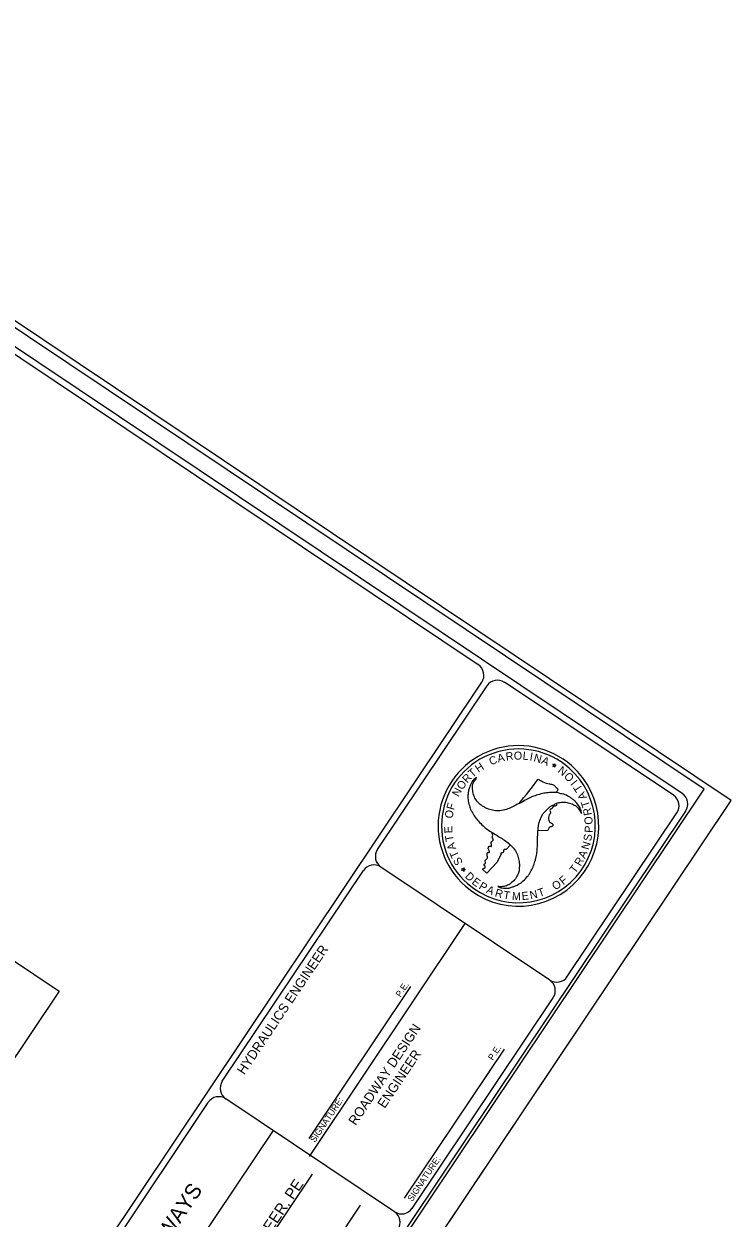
# Model space of a CAD drawing. Extents: x 1715610 to 1720914, y 798298 to 802505.
# Drawn here: x 1717939 to 1718775, y 801094 to 802505 of the extents above; entities that cross this region are included whole.
import ezdxf

# ---------------------------------------------------------------- set-up
doc = ezdxf.new("R2010")
doc.units = 0
for name, color, linetype in [('Prop DSN Text', 7, 'Continuous'), ('Sheet Cutting Line CELL', 7, 'Continuous'), ('Sheet Data Field CELL', 7, 'Continuous'), ('Sheet Plot Border Inside CELL', 7, 'Continuous'), ('Sheet Plot Border Outside CELL', 7, 'Continuous'), ('Sheet Title CELL', 7, 'Continuous')]:
    doc.layers.add(name, color=color, linetype=linetype)

msp = doc.modelspace()

# ---------------------------------------------------------------- linework, layer by layer
at = {"layer": 'Prop DSN Text'}
msp.add_lwpolyline([(1717114.5, 800787.1), (1717648.2, 801584.4), (1717980.5, 801362), (1717446.8, 800564.7)], close=True, dxfattribs=at)
at = {"layer": 'Sheet Cutting Line CELL'}
msp.add_line((1717369.7, 799488.2), (1718774.7, 801587.4), dxfattribs=at)
at = {"layer": 'Sheet Plot Border Inside CELL'}
msp.add_lwpolyline([(1717352.6, 799523.2), (1718743, 801600.5), (1717427.7, 802480.8), (1716037.3, 800403.5)], close=True, dxfattribs=at)
at = {"layer": 'Sheet Plot Border Outside CELL'}
msp.add_lwpolyline([(1717403.5, 802505.2), (1715998.5, 800406), (1717369.7, 799488.2), (1718774.7, 801587.4)], close=True, dxfattribs=at)
at = {"layer": 'Sheet Title CELL'}
for p, q in [((1717295.2, 799956.8), (1718480, 801726.9)), ((1718356.7, 801529.2), (1718486.2, 801722.7)), ((1718564.9, 801628.7), (1718563.8, 801627.5)), ((1718563.8, 801627.5), (1718565.4, 801627.9)), ((1718565.6, 801629.5), (1718564.1, 801630.1)), ((1718564.1, 801630.1), (1718564.9, 801628.7)), ((1718565.4, 801627.9), (1718566.3, 801626.5)), ((1718566.6, 801630.7), (1718565.6, 801629.5)), ((1718566.3, 801626.5), (1718566.4, 801628)), ((1718566.4, 801628), (1718568, 801628.4)), ((1718566.5, 801629.1), (1718566.6, 801630.7)), ((1718568, 801628.4), (1718566.5, 801629.1)), ((1718586, 801628.4), (1718586, 801628.4)), ((1718473.6, 801614.5), (1718473.6, 801614.2)), ((1718473.6, 801614.5), (1718473.6, 801614.2)), ((1718524, 801583.6), (1718524, 801583.6)), ((1718558.2, 801551.7), (1718546.4, 801551.4)), ((1718546.4, 801551.4), (1718546.4, 801551.4)), ((1718513.9, 801534.7), (1718508.9, 801529.1)), ((1718502.8, 801524), (1718498.2, 801514.2)), ((1718173.3, 801255.3), (1718340, 801504.3)), ((1718560.3, 801374.9), (1718360.8, 801508.4)), ((1718456.1, 801504.4), (1718457.2, 801505.7)), ((1718457.8, 801504.8), (1718456.1, 801504.4)), ((1718457.2, 801505.7), (1718456.4, 801507)), ((1718456.4, 801507), (1718457.9, 801506.4)), ((1718458.6, 801503.4), (1718457.8, 801504.8)), ((1718457.9, 801506.4), (1718459, 801507.7)), ((1718458.7, 801505), (1718458.6, 801503.4)), ((1718460.3, 801505.3), (1718458.7, 801505)), ((1718459, 801507.7), (1718458.8, 801506)), ((1718458.8, 801506), (1718460.3, 801505.3)), ((1718485.8, 801501.2), (1718481.7, 801505.1)), ((1718498.2, 801514.2), (1718485.8, 801501.2)), ((1718276.4, 801166.6), (1718460.5, 801441.7)), ((1718276, 801187.5), (1718396.3, 801367.3)), ((1718388.7, 801117), (1718506.7, 801293.4)), ((1717918.9, 800875.1), (1718156.7, 801230.4)), ((1718376.9, 801101), (1718177.5, 801234.5)), ((1718233.3, 801197.1), (1717978.8, 800816.9)), ((1718150.4, 800952), (1718279.8, 801145.4)), ((1718206.2, 800914), (1718336.6, 801108.8))]:
    msp.add_line(p, q, dxfattribs=at)
for points in [[(1718716.9, 801595.4), (1717432.9, 802454.8)], [(1718475.9, 801747.7), (1717435, 802444.4)], [(1718706.5, 801593.4), (1718507, 801726.9)], [(1717486.2, 799729.7), (1718721, 801574.6)], [(1718581.1, 801379.1), (1718710.6, 801572.6)], [(1718397.7, 801105.1), (1718564.4, 801354.1)]]:
    msp.add_lwpolyline(points, dxfattribs=at)
for centre, radius, start, end in [((1718467.5, 801735.3), 15, 326.2051, 56.2051), ((1718498.6, 801714.4), 15, 56.2051, 146.2051), ((1718523.3, 801557.2), 94.9, 48.6262, 228.6262), ((1718523.3, 801557.2), 90.9, 48.6262, 228.6262), ((1718523.3, 801557.2), 94.9, 228.6262, 48.6262), ((1718523.3, 801557.2), 90.9, 228.6262, 48.6262), ((1718142.2, 801906.9), 500.3, 319.7437, 323.9497), ((1718698.1, 801580.9), 15, 326.2051, 56.2051), ((1718708.5, 801583), 15, 326.2051, 56.2051), ((1718142.2, 801906.9), 500.3, 314.3047, 314.4043), ((1718369.2, 801520.9), 15, 146.2051, 236.2051), ((1718352.5, 801496), 15, 56.2051, 146.2051), ((1718568.6, 801387.5), 15, 236.2051, 326.2051), ((1718551.9, 801362.5), 15, 326.2051, 56.2051), ((1718185.8, 801247), 15, 146.2051, 236.2051), ((1718169.1, 801222.1), 15, 56.2051, 146.2051), ((1718385.2, 801113.5), 15, 236.2051, 326.2051), ((1718368.5, 801088.6), 15, 326.2051, 56.2051)]:
    msp.add_arc(centre, radius, start, end, dxfattribs=at)
for points in [[(1718473.6, 801614.2), (1718471.8, 801613), (1718467.8, 801608.1), (1718465.1, 801601.9), (1718464.9, 801601.3), (1718464.1, 801597.8), (1718463.7, 801593.5), (1718464, 801586.5), (1718465.9, 801579.5), (1718466.8, 801576.7), (1718468.4, 801573.7), (1718472, 801567.7), (1718476.1, 801562.6), (1718481.5, 801557.3), (1718486.6, 801553), (1718492.4, 801549.3), (1718498.3, 801545.7), (1718503.9, 801542.1), (1718509.7, 801538.2), (1718514.8, 801533.8), (1718515.2, 801533.4), (1718519.8, 801527.7), (1718522.6, 801521.3), (1718524.1, 801515), (1718524.5, 801511.7), (1718524.3, 801507.7), (1718524.2, 801505.4), (1718523, 801500.7), (1718519.8, 801494.8), (1718515.3, 801490.3), (1718510.5, 801487), (1718504.9, 801485.4), (1718498.9, 801485.5)], [(1718597.7, 801571.8), (1718597.6, 801573.9), (1718595.3, 801579.8), (1718591.3, 801585.3), (1718590.9, 801585.8), (1718588.2, 801588.2), (1718584.7, 801590.6), (1718578.5, 801594), (1718571.6, 801595.7), (1718568.7, 801596.5), (1718565.2, 801596.6), (1718558.3, 801596.4), (1718551.8, 801595.4), (1718544.5, 801593.4), (1718538.3, 801591.1), (1718532.1, 801587.9), (1718526.1, 801584.6), (1718520.1, 801581.6), (1718513.9, 801578.5), (1718507.5, 801576.3), (1718506.9, 801576.2), (1718499.6, 801575), (1718492.7, 801575.8), (1718486.5, 801577.6), (1718483.5, 801579), (1718480.1, 801581.2), (1718478.1, 801582.4), (1718474.8, 801585.8), (1718471.2, 801591.5), (1718469.5, 801597.6), (1718469.1, 801603.4), (1718470.6, 801609.1), (1718473.6, 801614.2), (1718473.6, 801614.5)], [(1718546.7, 801612.4), (1718552.3, 801609.3), (1718560.1, 801606.8), (1718564.6, 801605.7), (1718567.2, 801603.4), (1718569.8, 801600), (1718567.4, 801596.7)], [(1718567.4, 801596.6), (1718565.2, 801596.6), (1718558.3, 801596.4), (1718551.8, 801595.4), (1718544.5, 801593.4), (1718538.3, 801591.1), (1718532.1, 801587.9), (1718526.1, 801584.6), (1718524, 801583.6)], [(1718498.9, 801485.5), (1718500.9, 801484.6), (1718507.1, 801483.5), (1718513.8, 801484.2), (1718514.4, 801484.5), (1718518, 801485.5), (1718521.7, 801487.3), (1718527.8, 801491), (1718532.7, 801496.1), (1718534.8, 801498.3), (1718536.7, 801501.3), (1718539.9, 801507.3), (1718542.3, 801513.4), (1718544.2, 801520.8), (1718545.4, 801527.3), (1718545.7, 801534.2), (1718545.8, 801541.1), (1718546.2, 801547.8), (1718546.7, 801554.7), (1718548, 801561.4), (1718548.2, 801562), (1718550.8, 801568.9), (1718554.9, 801574.4), (1718559.5, 801578.9), (1718562.3, 801580.9), (1718565.9, 801582.6), (1718567.9, 801583.8), (1718572.6, 801585), (1718579.2, 801585.2), (1718585.3, 801583.6), (1718590.6, 801581.1), (1718594.8, 801577), (1718597.7, 801571.8)], [(1718546.4, 801551.4), (1718546.7, 801554.7), (1718548, 801561.4), (1718548.2, 801562), (1718550.8, 801568.9), (1718554.9, 801574.4), (1718559.5, 801578.9), (1718562.3, 801580.9), (1718565.9, 801582.6), (1718567.8, 801583.7)], [(1718567.8, 801583.7), (1718568.5, 801581.9), (1718567.6, 801580.8), (1718564.5, 801580.2), (1718562.9, 801577.5), (1718561.4, 801577), (1718560.7, 801576.3), (1718561.3, 801572.8), (1718559.8, 801570.1), (1718559.3, 801564), (1718560.2, 801561.8), (1718563.9, 801559.1), (1718563.8, 801557.6), (1718562.6, 801556.6), (1718559.7, 801555.1), (1718558.2, 801551.7)], [(1718481.7, 801505.1), (1718481.1, 801505.3), (1718481.3, 801506.4), (1718483.9, 801507.7), (1718483.9, 801509.5), (1718483, 801510.2), (1718482.9, 801511.8), (1718484.3, 801512.9), (1718483.9, 801515.5), (1718484.6, 801516.9), (1718486.7, 801519.3), (1718486.3, 801524.7), (1718487.2, 801526), (1718488.3, 801525.7), (1718489, 801526.3), (1718487.8, 801529.6), (1718487.7, 801530.2), (1718488.8, 801533.2), (1718489.7, 801533.4), (1718490.9, 801532.7), (1718491.4, 801532.8), (1718491.5, 801534), (1718491.2, 801536.1), (1718491.8, 801538.8), (1718493.9, 801540.7), (1718492.5, 801542.5), (1718493, 801546.4), (1718492.5, 801547.8), (1718491.6, 801548.8)], [(1718492.2, 801549.4), (1718492.4, 801549.3), (1718498.3, 801545.7), (1718503.9, 801542.1), (1718509.7, 801538.2), (1718513.9, 801534.7)], [(1718508.9, 801529.1), (1718507.4, 801529.5), (1718506.1, 801528.7), (1718505.6, 801526.5), (1718504.5, 801525.5), (1718502.6, 801525), (1718502.8, 801524)]]:
    msp.add_spline(points, degree=3, dxfattribs=at)

# ---------------------------------------------------------------- texts
at = {"layer": 'Sheet Data Field CELL'}
msp.add_text('JAMES A. SPEER, PE', height=13.125, rotation=56.2051, dxfattribs=at).set_placement((1718171.2, 800986.5))
at = {"layer": 'Sheet Title CELL'}
for s, height, rotation, p in [('O', 9.48, 0.4446, (1718517.9, 801635.5)), ('H', 9.45, 33.7676, (1718476, 801619.8)), ('C', 9.43, 21.4252, (1718490.7, 801628.6)), ('A', 9.46, 13.9282, (1718499.5, 801632)), ('R', 9.45, 7.5642, (1718508.9, 801634.3)), ('L', 9.44, 354.211, (1718528, 801635.6)), ('I', 9.48, 350.2216, (1718536.1, 801634.6)), ('N', 9.46, 344.5215, (1718540.6, 801633.7)), ('A', 9.46, 337.0895, (1718549.6, 801631.2)), ('R', 9.46, 47.5019, (1718462.8, 801607.1)), ('T', 9.48, 40.8523, (1718468.9, 801613.8)), ('N', 9.46, 140.8343, (1718582.1, 801622.8)), ('O', 9.43, 133.5863, (1718590, 801614.6)), ('O', 9.48, 54.1119, (1718457, 801599)), ('I', 9.49, 128.4507, (1718593.8, 801609.8)), ('T', 9.45, 122.8008, (1718599.7, 801600.9)), ('N', 9.46, 61.61, (1718452.5, 801590.9)), ('A', 9.48, 115.7163, (1718604.6, 801590.8)), ('O', 9.47, 80.8437, (1718445.4, 801565.5)), ('F', 9.48, 73.6969, (1718447, 801575.3)), ('T', 9.43, 107.6293, (1718608.1, 801580.7)), ('R', 9.48, 101.5295, (1718610.3, 801570.4)), ('O', 9.48, 94.3404, (1718611.2, 801559)), ('E', 9.43, 92.7831, (1718445.4, 801548.7)), ('S', 9.42, 80.4566, (1718609.2, 801538.6)), ('P', 9.46, 87.6484, (1718610.9, 801548.9)), ('T', 9.44, 99.8988, (1718446.9, 801539.6)), ('A', 9.49, 106.954, (1718449.8, 801530.2)), ('N', 9.43, 73.2461, (1718606.3, 801528.3)), ('T', 9.48, 114.0063, (1718453.4, 801521.7)), ('S', 9.45, 120.3824, (1718458, 801513.9)), ('R', 9.47, 59.4613, (1718596.8, 801508.9)), ('A', 9.43, 66.2145, (1718602, 801518)), ('T', 9.43, 52.5047, (1718590.4, 801500.3)), ('D', 9.46, 316.4792, (1718459.4, 801496.9)), ('E', 9.42, 322.7671, (1718467.4, 801489.5)), ('P', 9.46, 330.2995, (1718475.7, 801483.4)), ('O', 9.46, 32.4303, (1718566.7, 801480.8)), ('F', 9.45, 39.5955, (1718576.3, 801487)), ('A', 9.45, 336.892, (1718484.5, 801478.4)), ('R', 9.46, 343.9607, (1718494.8, 801474.1)), ('T', 9.45, 350.6112, (1718504.9, 801471.3)), ('M', 9.44, 357.8463, (1718515.5, 801469.7)), ('E', 9.44, 5.313, (1718527.5, 801469.5)), ('N', 9.48, 12.2846, (1718537.7, 801470.5)), ('T', 9.45, 19.1266, (1718548.1, 801472.9)), (' HYDRAULICS ENGINEER', 11.25, 56.2051, (1718196.9, 801258.8)), ('P.E.', 7.5, 56.2051, (1718383.8, 801354.1)), ('ROADWAY DESIGN', 11.249, 56.2051, (1718330.9, 801202.3)), ('P.E.', 7.5, 56.2051, (1718493, 801279.4)), ('ENGINEER', 11.25, 56.2051, (1718365.2, 801222.5)), ('SIGNATURE:', 7.5, 56.2051, (1718282.8, 801182.4)), ('SIGNATURE:', 7.5, 56.2051, (1718397.8, 801112.6)), ('DIVISION OF HIGHWAYS', 18.281, 56.2051, (1717990.4, 800887.7))]:
    msp.add_text(s, height=height, rotation=rotation, dxfattribs=at).set_placement(p)

doc.saveas('drawing.dxf')
